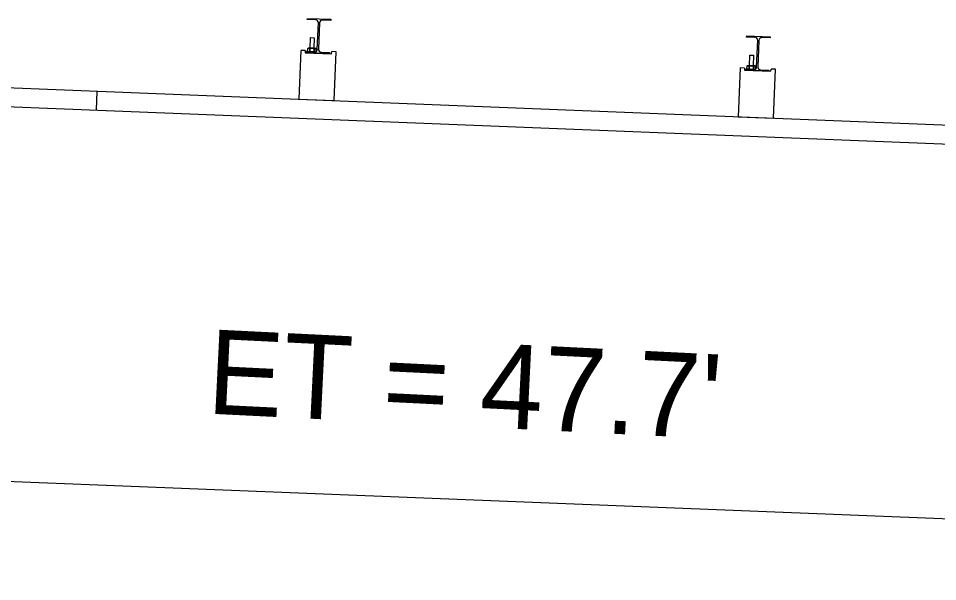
# Model space of a CAD drawing. Extents: x 16537443 to 16538473, y 7054586 to 7055469.
# Drawn here: x 16537720.15 to 16537733.22, y 7054749.62 to 7054757.63 of the extents above; entities that cross this region are included whole.
import ezdxf

# ---------------------------------------------------------------- set-up
doc = ezdxf.new("R2010")
doc.units = 0
doc.layers.add('Draft_DNC', color=7, linetype='Continuous')

msp = doc.modelspace()

# ---------------------------------------------------------------- linework, layer by layer
at = {"layer": 'Draft_DNC'}
for p, q in [((16537724.258, 7054757.616), (16537724.259, 7054757.631)), ((16537724.258, 7054757.616), (16537724.259, 7054757.631)), ((16537724.258, 7054757.616), (16537724.259, 7054757.631)), ((16537724.375, 7054757.611), (16537724.258, 7054757.616)), ((16537724.375, 7054757.611), (16537724.258, 7054757.616)), ((16537724.375, 7054757.611), (16537724.258, 7054757.616)), ((16537724.259, 7054757.631), (16537724.592, 7054757.618)), ((16537724.259, 7054757.631), (16537724.592, 7054757.618)), ((16537724.259, 7054757.631), (16537724.592, 7054757.618)), ((16537724.4, 7054757.193), (16537724.415, 7054757.568)), ((16537724.4, 7054757.193), (16537724.415, 7054757.568)), ((16537724.4, 7054757.193), (16537724.415, 7054757.568)), ((16537724.431, 7054757.567), (16537724.416, 7054757.192)), ((16537724.431, 7054757.567), (16537724.416, 7054757.192)), ((16537724.431, 7054757.567), (16537724.416, 7054757.192)), ((16537724.591, 7054757.602), (16537724.474, 7054757.607)), ((16537724.591, 7054757.602), (16537724.474, 7054757.607)), ((16537724.591, 7054757.602), (16537724.474, 7054757.607)), ((16537724.592, 7054757.618), (16537724.591, 7054757.602)), ((16537724.592, 7054757.618), (16537724.591, 7054757.602)), ((16537724.592, 7054757.618), (16537724.591, 7054757.602)), ((16537724.299, 7054757.207), (16537724.305, 7054757.358)), ((16537724.299, 7054757.207), (16537724.305, 7054757.358)), ((16537724.305, 7054757.358), (16537724.357, 7054757.356)), ((16537724.305, 7054757.358), (16537724.357, 7054757.356)), ((16537724.357, 7054757.356), (16537724.351, 7054757.205)), ((16537724.357, 7054757.356), (16537724.351, 7054757.205)), ((16537730.503, 7054757.366), (16537730.504, 7054757.381)), ((16537730.503, 7054757.366), (16537730.504, 7054757.381)), ((16537730.62, 7054757.361), (16537730.503, 7054757.366)), ((16537730.62, 7054757.361), (16537730.503, 7054757.366)), ((16537730.504, 7054757.381), (16537730.837, 7054757.368)), ((16537730.504, 7054757.381), (16537730.837, 7054757.368)), ((16537730.645, 7054756.943), (16537730.66, 7054757.318)), ((16537730.645, 7054756.943), (16537730.66, 7054757.318)), ((16537730.676, 7054757.317), (16537730.661, 7054756.943)), ((16537730.676, 7054757.317), (16537730.661, 7054756.943)), ((16537730.836, 7054757.352), (16537730.719, 7054757.357)), ((16537730.836, 7054757.352), (16537730.719, 7054757.357)), ((16537730.837, 7054757.368), (16537730.836, 7054757.352)), ((16537730.837, 7054757.368), (16537730.836, 7054757.352)), ((16537724.168, 7054757.176), (16537724.14, 7054756.481)), ((16537724.168, 7054757.176), (16537724.14, 7054756.481)), ((16537724.23, 7054757.174), (16537724.168, 7054757.176)), ((16537724.23, 7054757.174), (16537724.168, 7054757.176)), ((16537724.23, 7054757.174), (16537724.229, 7054757.142)), ((16537724.23, 7054757.174), (16537724.229, 7054757.142)), ((16537724.263, 7054757.162), (16537724.265, 7054757.204)), ((16537724.263, 7054757.162), (16537724.265, 7054757.204)), ((16537724.263, 7054757.162), (16537724.265, 7054757.204)), ((16537724.272, 7054757.156), (16537724.263, 7054757.162)), ((16537724.272, 7054757.156), (16537724.263, 7054757.162)), ((16537724.272, 7054757.156), (16537724.263, 7054757.162)), ((16537724.265, 7054757.204), (16537724.274, 7054757.208)), ((16537724.265, 7054757.204), (16537724.274, 7054757.208)), ((16537724.281, 7054757.208), (16537724.274, 7054757.208)), ((16537724.281, 7054757.208), (16537724.274, 7054757.208)), ((16537724.377, 7054757.204), (16537724.281, 7054757.208)), ((16537724.377, 7054757.204), (16537724.281, 7054757.208)), ((16537724.293, 7054757.161), (16537724.295, 7054757.202)), ((16537724.295, 7054757.202), (16537724.293, 7054757.161)), ((16537724.293, 7054757.161), (16537724.295, 7054757.202)), ((16537724.293, 7054757.161), (16537724.295, 7054757.202)), ((16537724.355, 7054757.2), (16537724.354, 7054757.158)), ((16537724.354, 7054757.158), (16537724.355, 7054757.2)), ((16537724.354, 7054757.158), (16537724.355, 7054757.2)), ((16537724.354, 7054757.158), (16537724.355, 7054757.2)), ((16537724.377, 7054757.204), (16537724.385, 7054757.199)), ((16537724.377, 7054757.204), (16537724.385, 7054757.199)), ((16537724.384, 7054757.161), (16537724.385, 7054757.199)), ((16537724.385, 7054757.199), (16537724.384, 7054757.161)), ((16537724.384, 7054757.161), (16537724.385, 7054757.199)), ((16537724.229, 7054757.142), (16537724.604, 7054757.127)), ((16537724.229, 7054757.142), (16537724.604, 7054757.127)), ((16537724.239, 7054757.142), (16537724.24, 7054757.158)), ((16537724.239, 7054757.142), (16537724.24, 7054757.158)), ((16537724.239, 7054757.142), (16537724.24, 7054757.158)), ((16537724.572, 7054757.129), (16537724.239, 7054757.142)), ((16537724.572, 7054757.129), (16537724.239, 7054757.142)), ((16537724.572, 7054757.129), (16537724.239, 7054757.142)), ((16537724.24, 7054757.158), (16537724.357, 7054757.153)), ((16537724.24, 7054757.158), (16537724.357, 7054757.153)), ((16537724.24, 7054757.158), (16537724.357, 7054757.153)), ((16537724.456, 7054757.149), (16537724.573, 7054757.144)), ((16537724.456, 7054757.149), (16537724.573, 7054757.144)), ((16537724.456, 7054757.149), (16537724.573, 7054757.144)), ((16537724.573, 7054757.144), (16537724.572, 7054757.129)), ((16537724.573, 7054757.144), (16537724.572, 7054757.129)), ((16537724.573, 7054757.144), (16537724.572, 7054757.129)), ((16537724.604, 7054757.127), (16537724.605, 7054757.159)), ((16537724.604, 7054757.127), (16537724.605, 7054757.159)), ((16537724.667, 7054757.156), (16537724.605, 7054757.159)), ((16537724.667, 7054757.156), (16537724.605, 7054757.159)), ((16537724.64, 7054756.461), (16537724.667, 7054757.156)), ((16537724.64, 7054756.461), (16537724.667, 7054757.156)), ((16537730.544, 7054756.958), (16537730.55, 7054757.109)), ((16537730.544, 7054756.958), (16537730.55, 7054757.109)), ((16537730.55, 7054757.109), (16537730.602, 7054757.106)), ((16537730.55, 7054757.109), (16537730.602, 7054757.106)), ((16537730.602, 7054757.106), (16537730.596, 7054756.956)), ((16537730.602, 7054757.106), (16537730.596, 7054756.956)), ((16537730.413, 7054756.926), (16537730.385, 7054756.231)), ((16537730.413, 7054756.926), (16537730.385, 7054756.231)), ((16537730.475, 7054756.924), (16537730.413, 7054756.926)), ((16537730.475, 7054756.924), (16537730.413, 7054756.926)), ((16537730.475, 7054756.924), (16537730.474, 7054756.893)), ((16537730.475, 7054756.924), (16537730.474, 7054756.893)), ((16537730.484, 7054756.892), (16537730.485, 7054756.908)), ((16537730.484, 7054756.892), (16537730.485, 7054756.908)), ((16537730.485, 7054756.908), (16537730.602, 7054756.903)), ((16537730.485, 7054756.908), (16537730.602, 7054756.903)), ((16537730.508, 7054756.912), (16537730.51, 7054756.954)), ((16537730.508, 7054756.912), (16537730.51, 7054756.954)), ((16537730.508, 7054756.912), (16537730.51, 7054756.954)), ((16537730.516, 7054756.907), (16537730.508, 7054756.912)), ((16537730.516, 7054756.907), (16537730.508, 7054756.912)), ((16537730.516, 7054756.907), (16537730.508, 7054756.912)), ((16537730.51, 7054756.954), (16537730.519, 7054756.959)), ((16537730.51, 7054756.954), (16537730.519, 7054756.959)), ((16537730.526, 7054756.958), (16537730.519, 7054756.959)), ((16537730.526, 7054756.958), (16537730.519, 7054756.959)), ((16537730.622, 7054756.954), (16537730.526, 7054756.958)), ((16537730.622, 7054756.954), (16537730.526, 7054756.958)), ((16537730.538, 7054756.911), (16537730.54, 7054756.953)), ((16537730.54, 7054756.953), (16537730.538, 7054756.911)), ((16537730.538, 7054756.911), (16537730.54, 7054756.953)), ((16537730.538, 7054756.911), (16537730.54, 7054756.953)), ((16537730.6, 7054756.95), (16537730.599, 7054756.909)), ((16537730.599, 7054756.909), (16537730.6, 7054756.95)), ((16537730.599, 7054756.909), (16537730.6, 7054756.95)), ((16537730.599, 7054756.909), (16537730.6, 7054756.95)), ((16537730.602, 7054756.903), (16537730.602, 7054756.903)), ((16537730.602, 7054756.903), (16537730.602, 7054756.903)), ((16537730.622, 7054756.954), (16537730.63, 7054756.949)), ((16537730.622, 7054756.954), (16537730.63, 7054756.949)), ((16537730.629, 7054756.911), (16537730.63, 7054756.949)), ((16537730.63, 7054756.949), (16537730.629, 7054756.911)), ((16537730.629, 7054756.911), (16537730.63, 7054756.949)), ((16537730.701, 7054756.899), (16537730.818, 7054756.895)), ((16537730.701, 7054756.899), (16537730.818, 7054756.895)), ((16537730.849, 7054756.878), (16537730.85, 7054756.909)), ((16537730.849, 7054756.878), (16537730.85, 7054756.909)), ((16537730.912, 7054756.906), (16537730.85, 7054756.909)), ((16537730.912, 7054756.906), (16537730.85, 7054756.909)), ((16537730.885, 7054756.211), (16537730.912, 7054756.906)), ((16537730.885, 7054756.211), (16537730.912, 7054756.906)), ((16537730.474, 7054756.893), (16537730.849, 7054756.878)), ((16537730.474, 7054756.893), (16537730.849, 7054756.878)), ((16537730.817, 7054756.879), (16537730.484, 7054756.892)), ((16537730.817, 7054756.879), (16537730.484, 7054756.892)), ((16537730.818, 7054756.895), (16537730.817, 7054756.879)), ((16537730.818, 7054756.895), (16537730.817, 7054756.879)), ((16537717.573, 7054756.743), (16537758.74, 7054755.096)), ((16537721.267, 7054756.595), (16537721.257, 7054756.325)), ((16537717.562, 7054756.473), (16537758.729, 7054754.826)), ((16537724.14, 7054756.481), (16537724.64, 7054756.461)), ((16537730.385, 7054756.231), (16537730.885, 7054756.211)), ((16537730.385, 7054756.231), (16537730.885, 7054756.211)), ((16537755.615, 7054749.616), (16537707.953, 7054751.522))]:
    msp.add_line(p, q, dxfattribs=at)
for points in [[(16537724.299, 7054757.207), (16537724.305, 7054757.358), (16537724.357, 7054757.356), (16537724.351, 7054757.205)], [(16537730.544, 7054756.958), (16537730.55, 7054757.109), (16537730.602, 7054757.106), (16537730.596, 7054756.956)]]:
    msp.add_lwpolyline(points, close=True, dxfattribs=at)
for points in [[(16537724.265, 7054757.204), (16537724.274, 7054757.208), (16537724.281, 7054757.208), (16537724.377, 7054757.204), (16537724.385, 7054757.199)], [(16537724.384, 7054757.161), (16537724.384, 7054757.161)], [(16537724.357, 7054757.153), (16537724.272, 7054757.156), (16537724.272, 7054757.156)], [(16537730.51, 7054756.954), (16537730.519, 7054756.959), (16537730.526, 7054756.958), (16537730.622, 7054756.954), (16537730.63, 7054756.949)], [(16537730.602, 7054756.903), (16537730.516, 7054756.907), (16537730.516, 7054756.907)], [(16537730.629, 7054756.911), (16537730.629, 7054756.911)]]:
    msp.add_lwpolyline(points, dxfattribs=at)
for centre, start, end in [((16537724.374, 7054757.569), 357.7129, 87.7019), ((16537724.374, 7054757.569), 357.7129, 87.7019), ((16537724.374, 7054757.569), 357.7129, 87.7019), ((16537724.473, 7054757.565), 87.7068, 177.7159), ((16537724.473, 7054757.565), 87.7068, 177.7159), ((16537724.473, 7054757.565), 87.7068, 177.7159), ((16537730.619, 7054757.319), 357.7129, 87.7019), ((16537730.619, 7054757.319), 357.7129, 87.7019), ((16537730.718, 7054757.316), 87.7068, 177.7159), ((16537730.718, 7054757.316), 87.7068, 177.7159), ((16537724.359, 7054757.195), 267.7068, 357.7159), ((16537724.359, 7054757.195), 267.7068, 357.7159), ((16537724.359, 7054757.195), 267.7068, 357.7159), ((16537724.359, 7054757.195), 267.7068, 306.8227), ((16537724.458, 7054757.191), 177.7129, 267.7019), ((16537724.458, 7054757.191), 177.7129, 267.7019), ((16537724.458, 7054757.191), 177.7129, 267.7019), ((16537730.604, 7054756.945), 267.7068, 357.7159), ((16537730.604, 7054756.945), 267.7068, 357.7159), ((16537730.604, 7054756.945), 267.7068, 306.8227), ((16537730.604, 7054756.945), 267.7068, 267.7078), ((16537730.703, 7054756.941), 177.7129, 267.7019), ((16537730.703, 7054756.941), 177.7129, 267.7019)]:
    msp.add_arc(centre, 0.0417, start, end, dxfattribs=at)
for points in [[(16537724.293, 7054757.161), (16537724.292, 7054757.16), (16537724.289, 7054757.158), (16537724.282, 7054757.156), (16537724.275, 7054757.156), (16537724.268, 7054757.159), (16537724.265, 7054757.161), (16537724.263, 7054757.162)], [(16537724.293, 7054757.161), (16537724.292, 7054757.16), (16537724.289, 7054757.158), (16537724.282, 7054757.156), (16537724.275, 7054757.156), (16537724.268, 7054757.159), (16537724.265, 7054757.161), (16537724.263, 7054757.162)], [(16537724.263, 7054757.162), (16537724.265, 7054757.161), (16537724.268, 7054757.159), (16537724.275, 7054757.156), (16537724.282, 7054757.156), (16537724.289, 7054757.158), (16537724.292, 7054757.16), (16537724.293, 7054757.161)], [(16537724.293, 7054757.161), (16537724.292, 7054757.16), (16537724.289, 7054757.158), (16537724.282, 7054757.156), (16537724.275, 7054757.156), (16537724.268, 7054757.159), (16537724.265, 7054757.161), (16537724.263, 7054757.162)], [(16537724.265, 7054757.204), (16537724.267, 7054757.204), (16537724.27, 7054757.206), (16537724.277, 7054757.208), (16537724.284, 7054757.208), (16537724.29, 7054757.205), (16537724.294, 7054757.203), (16537724.295, 7054757.202)], [(16537724.265, 7054757.204), (16537724.267, 7054757.204), (16537724.27, 7054757.206), (16537724.277, 7054757.208), (16537724.284, 7054757.208), (16537724.29, 7054757.205), (16537724.294, 7054757.203), (16537724.295, 7054757.202)], [(16537724.295, 7054757.202), (16537724.294, 7054757.203), (16537724.29, 7054757.205), (16537724.284, 7054757.208), (16537724.277, 7054757.208), (16537724.27, 7054757.206), (16537724.267, 7054757.204), (16537724.265, 7054757.204)], [(16537724.265, 7054757.204), (16537724.267, 7054757.204), (16537724.27, 7054757.206), (16537724.277, 7054757.208), (16537724.284, 7054757.208), (16537724.29, 7054757.205), (16537724.294, 7054757.203), (16537724.295, 7054757.202)], [(16537724.354, 7054757.158), (16537724.348, 7054757.157), (16537724.337, 7054757.155), (16537724.322, 7054757.154), (16537724.307, 7054757.156), (16537724.298, 7054757.159), (16537724.293, 7054757.161)], [(16537724.354, 7054757.158), (16537724.348, 7054757.157), (16537724.337, 7054757.155), (16537724.322, 7054757.154), (16537724.307, 7054757.156), (16537724.298, 7054757.159), (16537724.293, 7054757.161)], [(16537724.293, 7054757.161), (16537724.298, 7054757.159), (16537724.307, 7054757.156), (16537724.322, 7054757.154), (16537724.337, 7054757.155), (16537724.348, 7054757.157), (16537724.354, 7054757.158)], [(16537724.354, 7054757.158), (16537724.348, 7054757.157), (16537724.337, 7054757.155), (16537724.322, 7054757.154), (16537724.307, 7054757.156), (16537724.298, 7054757.159), (16537724.293, 7054757.161)], [(16537724.295, 7054757.202), (16537724.3, 7054757.204), (16537724.311, 7054757.206), (16537724.327, 7054757.207), (16537724.342, 7054757.204), (16537724.351, 7054757.201), (16537724.355, 7054757.2)], [(16537724.295, 7054757.202), (16537724.3, 7054757.204), (16537724.311, 7054757.206), (16537724.327, 7054757.207), (16537724.342, 7054757.204), (16537724.351, 7054757.201), (16537724.355, 7054757.2)], [(16537724.355, 7054757.2), (16537724.351, 7054757.201), (16537724.342, 7054757.204), (16537724.327, 7054757.207), (16537724.311, 7054757.206), (16537724.3, 7054757.204), (16537724.295, 7054757.202)], [(16537724.295, 7054757.202), (16537724.3, 7054757.204), (16537724.311, 7054757.206), (16537724.327, 7054757.207), (16537724.342, 7054757.204), (16537724.351, 7054757.201), (16537724.355, 7054757.2)], [(16537724.355, 7054757.2), (16537724.358, 7054757.201), (16537724.363, 7054757.204), (16537724.371, 7054757.205), (16537724.379, 7054757.203), (16537724.383, 7054757.2), (16537724.385, 7054757.199)], [(16537724.355, 7054757.2), (16537724.358, 7054757.201), (16537724.363, 7054757.204), (16537724.371, 7054757.205), (16537724.379, 7054757.203), (16537724.383, 7054757.2), (16537724.385, 7054757.199)], [(16537724.385, 7054757.199), (16537724.383, 7054757.2), (16537724.379, 7054757.203), (16537724.371, 7054757.205), (16537724.363, 7054757.204), (16537724.358, 7054757.201), (16537724.355, 7054757.2)], [(16537724.355, 7054757.2), (16537724.358, 7054757.201), (16537724.363, 7054757.204), (16537724.371, 7054757.205), (16537724.379, 7054757.203), (16537724.383, 7054757.2), (16537724.385, 7054757.199)], [(16537724.363, 7054757.154), (16537724.362, 7054757.154), (16537724.359, 7054757.155), (16537724.356, 7054757.157), (16537724.354, 7054757.158)], [(16537724.363, 7054757.154), (16537724.362, 7054757.154), (16537724.359, 7054757.155), (16537724.356, 7054757.157), (16537724.354, 7054757.158)], [(16537730.538, 7054756.911), (16537730.537, 7054756.91), (16537730.533, 7054756.908), (16537730.527, 7054756.906), (16537730.52, 7054756.907), (16537730.513, 7054756.909), (16537730.51, 7054756.911), (16537730.508, 7054756.912)], [(16537730.538, 7054756.911), (16537730.537, 7054756.91), (16537730.533, 7054756.908), (16537730.527, 7054756.906), (16537730.52, 7054756.907), (16537730.513, 7054756.909), (16537730.51, 7054756.911), (16537730.508, 7054756.912)], [(16537730.508, 7054756.912), (16537730.51, 7054756.911), (16537730.513, 7054756.909), (16537730.52, 7054756.907), (16537730.527, 7054756.906), (16537730.533, 7054756.908), (16537730.537, 7054756.91), (16537730.538, 7054756.911)], [(16537730.538, 7054756.911), (16537730.537, 7054756.91), (16537730.533, 7054756.908), (16537730.527, 7054756.906), (16537730.52, 7054756.907), (16537730.513, 7054756.909), (16537730.51, 7054756.911), (16537730.508, 7054756.912)], [(16537730.51, 7054756.954), (16537730.512, 7054756.955), (16537730.515, 7054756.956), (16537730.522, 7054756.958), (16537730.529, 7054756.958), (16537730.535, 7054756.956), (16537730.539, 7054756.953), (16537730.54, 7054756.953)], [(16537730.51, 7054756.954), (16537730.512, 7054756.955), (16537730.515, 7054756.956), (16537730.522, 7054756.958), (16537730.529, 7054756.958), (16537730.535, 7054756.956), (16537730.539, 7054756.953), (16537730.54, 7054756.953)], [(16537730.54, 7054756.953), (16537730.539, 7054756.953), (16537730.535, 7054756.956), (16537730.529, 7054756.958), (16537730.522, 7054756.958), (16537730.515, 7054756.956), (16537730.512, 7054756.955), (16537730.51, 7054756.954)], [(16537730.51, 7054756.954), (16537730.512, 7054756.955), (16537730.515, 7054756.956), (16537730.522, 7054756.958), (16537730.529, 7054756.958), (16537730.535, 7054756.956), (16537730.539, 7054756.953), (16537730.54, 7054756.953)], [(16537730.599, 7054756.909), (16537730.593, 7054756.907), (16537730.582, 7054756.905), (16537730.567, 7054756.904), (16537730.552, 7054756.907), (16537730.543, 7054756.909), (16537730.538, 7054756.911)], [(16537730.599, 7054756.909), (16537730.593, 7054756.907), (16537730.582, 7054756.905), (16537730.567, 7054756.904), (16537730.552, 7054756.907), (16537730.543, 7054756.909), (16537730.538, 7054756.911)], [(16537730.538, 7054756.911), (16537730.543, 7054756.909), (16537730.552, 7054756.907), (16537730.567, 7054756.904), (16537730.582, 7054756.905), (16537730.593, 7054756.907), (16537730.599, 7054756.909)], [(16537730.599, 7054756.909), (16537730.593, 7054756.907), (16537730.582, 7054756.905), (16537730.567, 7054756.904), (16537730.552, 7054756.907), (16537730.543, 7054756.909), (16537730.538, 7054756.911)], [(16537730.54, 7054756.953), (16537730.545, 7054756.954), (16537730.556, 7054756.956), (16537730.572, 7054756.957), (16537730.587, 7054756.955), (16537730.596, 7054756.952), (16537730.6, 7054756.95)], [(16537730.54, 7054756.953), (16537730.545, 7054756.954), (16537730.556, 7054756.956), (16537730.572, 7054756.957), (16537730.587, 7054756.955), (16537730.596, 7054756.952), (16537730.6, 7054756.95)], [(16537730.6, 7054756.95), (16537730.596, 7054756.952), (16537730.587, 7054756.955), (16537730.572, 7054756.957), (16537730.556, 7054756.956), (16537730.545, 7054756.954), (16537730.54, 7054756.953)], [(16537730.54, 7054756.953), (16537730.545, 7054756.954), (16537730.556, 7054756.956), (16537730.572, 7054756.957), (16537730.587, 7054756.955), (16537730.596, 7054756.952), (16537730.6, 7054756.95)], [(16537730.6, 7054756.95), (16537730.603, 7054756.951), (16537730.608, 7054756.954), (16537730.616, 7054756.955), (16537730.624, 7054756.953), (16537730.628, 7054756.95), (16537730.63, 7054756.949)], [(16537730.6, 7054756.95), (16537730.603, 7054756.951), (16537730.608, 7054756.954), (16537730.616, 7054756.955), (16537730.624, 7054756.953), (16537730.628, 7054756.95), (16537730.63, 7054756.949)], [(16537730.63, 7054756.949), (16537730.628, 7054756.95), (16537730.624, 7054756.953), (16537730.616, 7054756.955), (16537730.608, 7054756.954), (16537730.603, 7054756.951), (16537730.6, 7054756.95)], [(16537730.6, 7054756.95), (16537730.603, 7054756.951), (16537730.608, 7054756.954), (16537730.616, 7054756.955), (16537730.624, 7054756.953), (16537730.628, 7054756.95), (16537730.63, 7054756.949)], [(16537730.608, 7054756.904), (16537730.607, 7054756.904), (16537730.604, 7054756.905), (16537730.601, 7054756.907), (16537730.599, 7054756.909)], [(16537730.608, 7054756.904), (16537730.607, 7054756.904), (16537730.604, 7054756.905), (16537730.601, 7054756.907), (16537730.599, 7054756.909)]]:
    msp.add_open_spline(points, degree=3, dxfattribs=at)

# ---------------------------------------------------------------- texts
msp.add_text("ET = 47.7'", height=1.2, rotation=357.1552, dxfattribs=at).set_placement((16537722.819, 7054752.008))

doc.saveas('drawing.dxf')
